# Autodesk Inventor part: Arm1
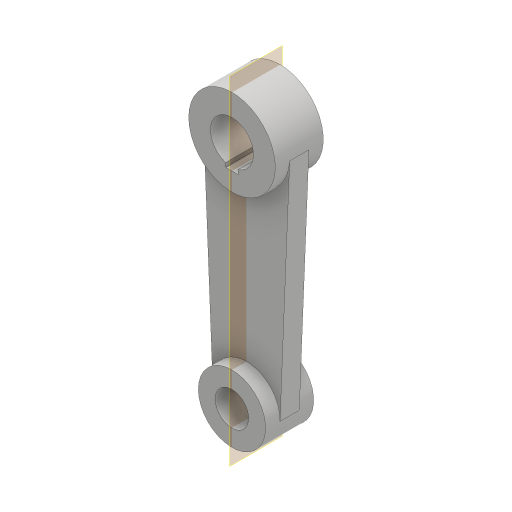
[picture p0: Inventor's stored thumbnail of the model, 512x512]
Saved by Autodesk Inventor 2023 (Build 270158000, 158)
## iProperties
Created: 2016-05
Part Number: Arm1
Material: Generic
Document SubType Name: Modeling
Designer: CADCIM
Density: 1 g/cm^3
Appearance: Default
Author: CADCIM
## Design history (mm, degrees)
sketch "Sketch1"
  geometry: C1 r 56.25 at (0, 0); C2 r 28 at (0, 0); C3 r 43.75 at (0, -300); C4 r 21.75 at (0, -300); 1 further point
  constraints: 4 centre point, 3 coincident
  dimensions: "d0" = 112.5 diameter of C1; "d1" = 56 diameter of C2; "d2" = 87.5 diameter of C3; "d3" = 43.5 diameter of C4; "d4" = 300 distance of C4.centre C2.centre
extrude "Extrusion1" new body sketch "Sketch1" stored distance "d5" = 62.5; taper "d6" = 0 deg
sketch "Sketch2"
  geometry: L1 (56.201, -2.344)-(43.712, -301.823); L2 (-56.201, -2.344)-(-43.712, -301.823); A1 r 56.25 centre (0, 0) between (-56.201, -2.344) and (56.201, -2.344); A2 r 43.75 centre (0, -300) between (43.712, -301.823) and (-43.712, -301.823); 3 further points
  constraints: 4 end point, 4 point on circle, 2 centre point, 2 coincident
extrude "Extrusion2" join sketch "Sketch2" stored distance "d7" = 25; taper "d8" = 0 deg
sketch "Sketch3"
  geometry: L1 (0, 0)-(0, 99.622); L2 (-8, 26.833)-(8, 26.833); L3 (8, 26.833)-(8, 32.3); L4 (8, 32.3)-(-8, 32.3); L5 (-8, 32.3)-(-8, 26.833); L6 (0, 0)-(0, -28); A1 r 28 centre (0, 0) between (-8, 26.833) and (8, 26.833) reference
  constraints: 12 end point, 3 point on circle, 2 parallel, 2 vertical, 1 horizontal, 1 perpendicular, 1 other
  dimensions: "d10" = 16 distance of L3.end L4.end; "d11" = 60.3 distance from line of L4 L6.end
extrude "Extrusion3" cut sketch "Sketch3" extent not by distance; stored distance "d12" = 25; taper "d13" = 0 deg
fillet "Fillet1" dims "d14" = 0.4
body "Solid1"
